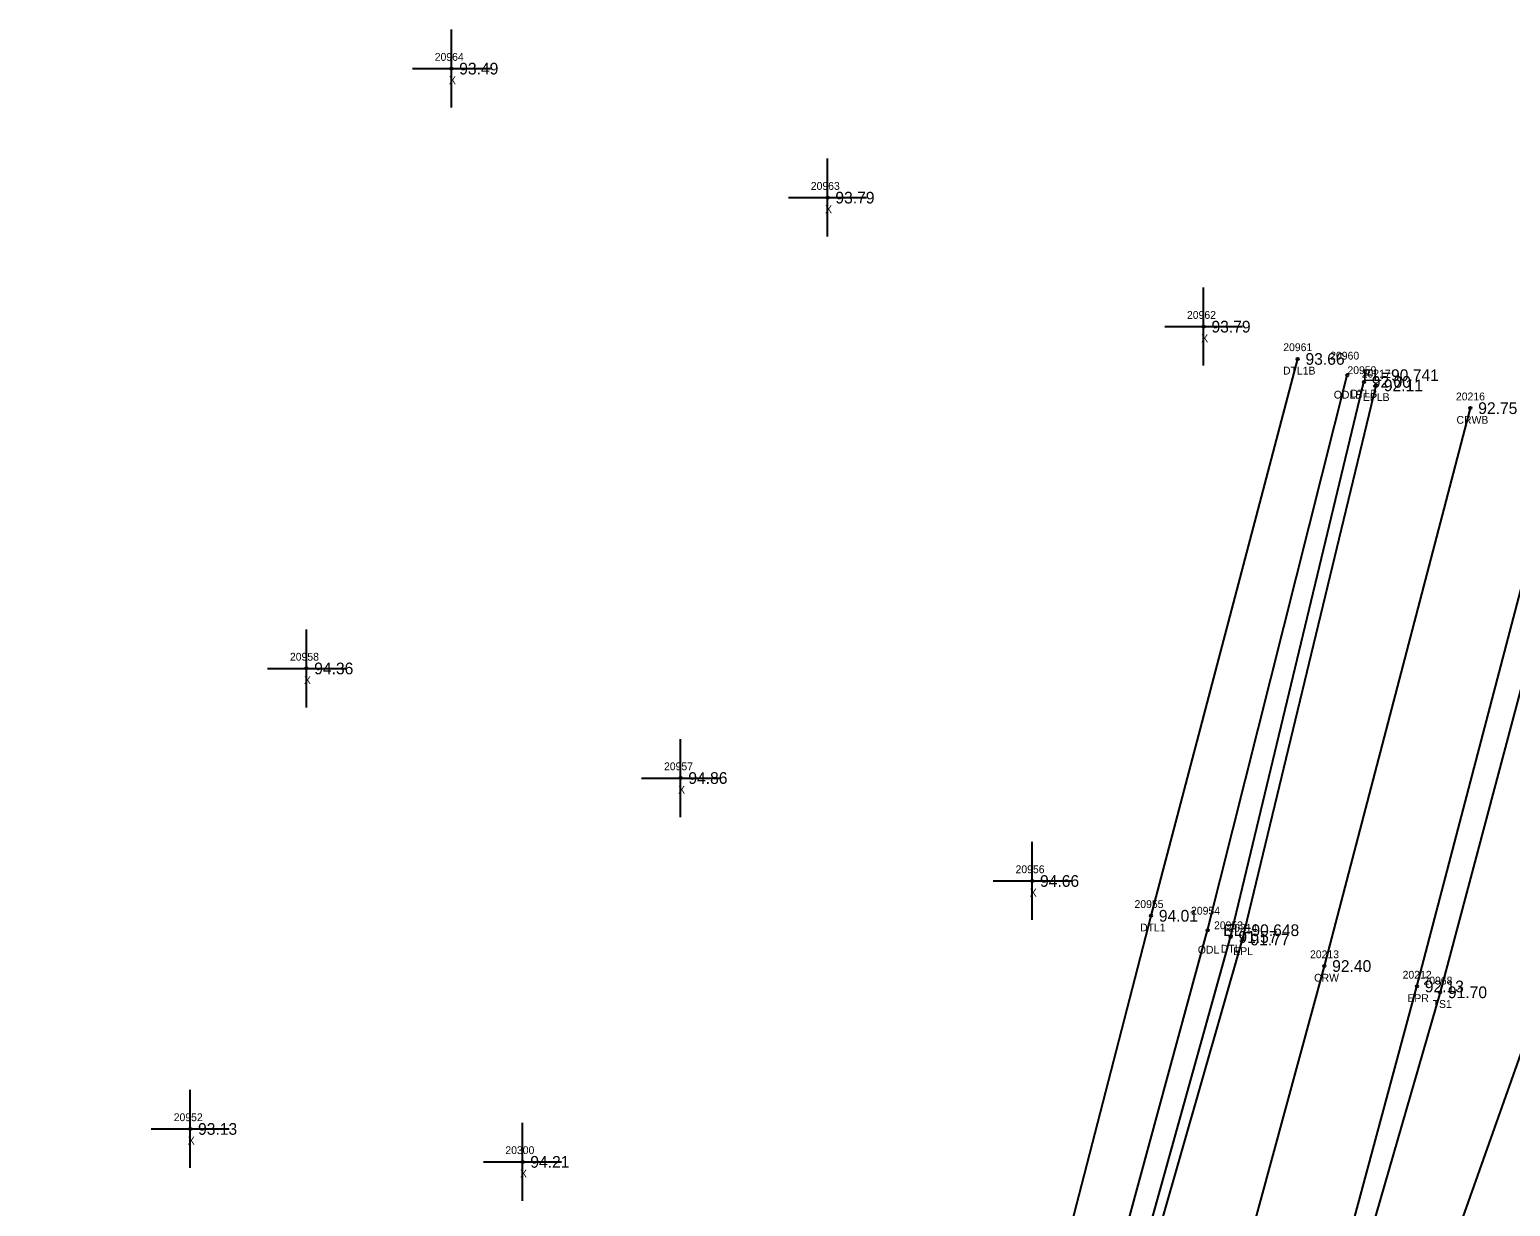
# Model space of a CAD drawing. Extents: x 2530197 to 2532051, y 935230 to 936631.
# Drawn here: x 2531647.6 to 2531837.5, y 936480.5 to 936631.4 of the extents above; entities that cross this region are included whole.
import ezdxf

# ---------------------------------------------------------------- set-up
doc = ezdxf.new("R2010")
doc.units = 0
for name, color, linetype in [('RD_DTM_BkLn1', 7, 'Continuous'), ('RD_DTM_BkLn2', 7, 'Continuous'), ('RD_DTM_BkLn_txCode', 7, 'Continuous'), ('RD_EX_H2O', 7, 'Continuous'), ('RD_EX_H2O_txCode', 7, 'Continuous'), ('RD_EX_Misc', 7, 'Continuous'), ('RD_EX_Misc_txCode', 7, 'Continuous'), ('RD_EX_Road', 7, 'Continuous'), ('RD_EX_Road_txCode', 7, 'Continuous'), ('RD_EX_TX_H2O_ELEV', 7, 'Continuous'), ('RD_EX_TX_Misc_ELEV', 7, 'Continuous'), ('RD_EX_TX_Road_ELEV', 7, 'Continuous'), ('RD_HC_Survey_ELEV', 7, 'Continuous'), ('RD_HC_Survey_txCode', 7, 'Continuous'), ('RD_SMD_Locator', 7, 'Continuous')]:
    doc.layers.add(name, color=color, linetype=linetype)

msp = doc.modelspace()

# ---------------------------------------------------------------- linework, layer by layer
at = {"layer": 'RD_DTM_BkLn1'}
msp.add_lwpolyline([(2531175.16, 935992.09), (2531214.08, 936014.93), (2531297.2, 936064.16), (2531382.2, 936114.3), (2531466.12, 936163.77), (2531548.89, 936212.96), (2531632.55, 936261.89), (2531678, 936289.19), (2531722.34, 936315.93), (2531754.26, 936342.49), (2531759.78, 936349.83), (2531772.77, 936373.29), (2531778.96, 936389.71), (2531793.78, 936438.29), (2531813.65, 936511.36), (2531832.39, 936582.88)], dxfattribs=at)
at = {"layer": 'RD_DTM_BkLn2'}
for points in [[(2531847.31, 936578.71), (2531828.5, 936507.99), (2531807.07, 936433.9), (2531793.16, 936383.74), (2531787.14, 936359.39), (2531794.14, 936352.47)], [(2531858.76, 936574.82), (2531840.28, 936504.17), (2531814.37, 936431.07), (2531798.77, 936381.67), (2531794.1, 936358.42), (2531794.14, 936352.47)]]:
    msp.add_lwpolyline(points, dxfattribs=at)
at = {"layer": 'RD_EX_H2O'}
for points in [[(2531765.74, 936419.97), (2531768.07, 936430.45), (2531772.65, 936445.12), (2531791.42, 936517.8), (2531810.23, 936589.19)], [(2531765.74, 936419.97), (2531771.25, 936418.23), (2531776.62, 936427.07), (2531781.23, 936441.81), (2531801.62, 936515.08), (2531818.73, 936586.25)], [(2531770.23, 936422.22), (2531778.73, 936442.72), (2531798.67, 936515.95), (2531816.58, 936587.11)]]:
    msp.add_lwpolyline(points, dxfattribs=at)
at = {"layer": 'RD_EX_Misc'}
for p, q in [((2531701.68, 936621.41), (2531701.68, 936631.41)), ((2531696.68, 936626.41), (2531706.68, 936626.41)), ((2531749.93, 936604.87), (2531749.93, 936614.87)), ((2531744.93, 936609.87), (2531754.93, 936609.87)), ((2531798.17, 936588.33), (2531798.17, 936598.33)), ((2531793.17, 936593.33), (2531803.17, 936593.33)), ((2531683.08, 936544.51), (2531683.08, 936554.51)), ((2531678.08, 936549.51), (2531688.08, 936549.51)), ((2531731.07, 936530.46), (2531731.07, 936540.46)), ((2531726.07, 936535.46), (2531736.07, 936535.46)), ((2531776.18, 936517.26), (2531776.18, 936527.26)), ((2531771.18, 936522.26), (2531781.18, 936522.26)), ((2531668.18, 936485.47), (2531668.18, 936495.47)), ((2531710.8, 936481.25), (2531710.8, 936491.25)), ((2531663.18, 936490.47), (2531673.18, 936490.47)), ((2531705.8, 936486.25), (2531715.8, 936486.25))]:
    msp.add_line(p, q, dxfattribs=at)
at = {"layer": 'RD_EX_Road'}
for points in [[(2531169.65, 936000.77), (2531208.79, 936024.95), (2531292.04, 936074.02), (2531376.24, 936123.7), (2531460.37, 936174.49), (2531542.92, 936223.44), (2531626.67, 936270.85), (2531672.4, 936298.39), (2531714.28, 936327.21), (2531747.19, 936360.45), (2531761.42, 936377.32), (2531773.11, 936411.11), (2531782.2, 936441.65), (2531803.17, 936514.76), (2531820.28, 936585.8)], [(2531180.82, 935982), (2531220.82, 936004.21), (2531303.54, 936053.39), (2531388.75, 936103.71), (2531472.27, 936152.98), (2531554.79, 936201.9), (2531638.11, 936250.92), (2531683.19, 936278.28), (2531730.37, 936304.55), (2531771.5, 936341.26), (2531788.67, 936375.53), (2531805.57, 936434.84), (2531825.53, 936508.74), (2531844.13, 936579.65)]]:
    msp.add_lwpolyline(points, dxfattribs=at)
at = {"layer": 'RD_SMD_Locator'}
for centre in [(2531701.68, 936626.41), (2531749.93, 936609.87), (2531798.17, 936593.33), (2531810.23, 936589.19), (2531816.58, 936587.11), (2531818.73, 936586.25), (2531820.28, 936585.8), (2531832.39, 936582.88), (2531683.08, 936549.51), (2531731.07, 936535.46), (2531776.18, 936522.26), (2531791.42, 936517.8), (2531798.67, 936515.95), (2531801.62, 936515.08), (2531803.17, 936514.76), (2531813.65, 936511.36), (2531825.53, 936508.74), (2531828.5, 936507.99), (2531668.18, 936490.47), (2531710.8, 936486.25)]:
    msp.add_circle(centre, 0.15, dxfattribs=at)

# ---------------------------------------------------------------- texts
at = {"layer": 'RD_DTM_BkLn_txCode'}
for s, p in [('20968', (2531826.36, 936508.99)), ('TS1', (2531827.54, 936505.99))]:
    msp.add_text(s, height=1, dxfattribs=at).set_placement(p)
at = {"layer": 'RD_EX_H2O_txCode'}
for s, p in [('20961', (2531808.38, 936590.19)), ('20960', (2531814.4, 936589.11)), ('DTL1B', (2531808.35, 936587.19)), ('20959', (2531816.61, 936587.25)), ('ODLB', (2531814.86, 936584.11)), ('DTLB', (2531817.02, 936584.25)), ('20955', (2531789.3, 936518.8)), ('20954', (2531796.55, 936517.95)), ('DTL1', (2531790.01, 936515.8)), ('20953', (2531799.5, 936516.08)), ('ODL', (2531797.42, 936512.95)), ('DTL', (2531800.37, 936513.08))]:
    msp.add_text(s, height=1, dxfattribs=at).set_placement(p)
at = {"layer": 'RD_EX_Misc_txCode'}
for s, p in [('20964', (2531699.54, 936627.41)), ('X', (2531701.37, 936624.41)), ('20963', (2531747.78, 936610.87)), ('X', (2531749.61, 936607.87)), ('20962', (2531796.03, 936594.33)), ('X', (2531797.85, 936591.33)), ('20958', (2531680.97, 936550.51)), ('X', (2531682.77, 936547.51)), ('20957', (2531728.95, 936536.46)), ('X', (2531730.76, 936533.46)), ('20956', (2531774.04, 936523.26)), ('X', (2531775.86, 936520.26)), ('20952', (2531666.06, 936491.47)), ('X', (2531667.86, 936488.47)), ('20300', (2531708.6, 936487.25)), ('X', (2531710.48, 936484.25))]:
    msp.add_text(s, height=1, dxfattribs=at).set_placement(p)
at = {"layer": 'RD_EX_Road_txCode'}
for s, p in [('20217', (2531818.44, 936586.8)), ('EPLB', (2531818.6, 936583.8)), ('20214', (2531801.34, 936515.76)), ('EPL', (2531801.97, 936512.76)), ('20212', (2531823.69, 936509.74)), ('EPR', (2531824.3, 936506.74))]:
    msp.add_text(s, height=1, dxfattribs=at).set_placement(p)
at = {"layer": 'RD_EX_TX_H2O_ELEV'}
for s, p in [('93.66', (2531811.23, 936588.44)), ('EL=90.741', (2531818.58, 936586.36)), ('92.00', (2531819.73, 936585.5)), ('94.01', (2531792.42, 936517.05)), ('EL=90.648', (2531800.67, 936515.2)), ('91.57', (2531802.62, 936514.33))]:
    msp.add_text(s, height=1.5, dxfattribs=at).set_placement(p)
at = {"layer": 'RD_EX_TX_Misc_ELEV'}
for s, p in [('93.49', (2531702.68, 936625.66)), ('93.79', (2531750.93, 936609.12)), ('93.79', (2531799.17, 936592.58)), ('94.36', (2531684.08, 936548.76)), ('94.86', (2531732.07, 936534.71)), ('94.66', (2531777.18, 936521.51)), ('91.70', (2531829.5, 936507.24)), ('93.13', (2531669.18, 936489.72)), ('94.21', (2531711.8, 936485.5))]:
    msp.add_text(s, height=1.5, dxfattribs=at).set_placement(p)
at = {"layer": 'RD_EX_TX_Road_ELEV'}
for s, p in [('92.11', (2531821.28, 936585.05)), ('91.77', (2531804.17, 936514.01)), ('92.13', (2531826.53, 936507.99))]:
    msp.add_text(s, height=1.5, dxfattribs=at).set_placement(p)
at = {"layer": 'RD_HC_Survey_ELEV'}
for s, p in [('92.75', (2531833.39, 936582.13)), ('92.40', (2531814.65, 936510.61))]:
    msp.add_text(s, height=1.5, dxfattribs=at).set_placement(p)
at = {"layer": 'RD_HC_Survey_txCode'}
for s, p in [('20216', (2531830.53, 936583.88)), ('CRWB', (2531830.6, 936580.88)), ('20213', (2531811.81, 936512.36)), ('CRW', (2531812.33, 936509.36))]:
    msp.add_text(s, height=1, dxfattribs=at).set_placement(p)

doc.saveas('drawing.dxf')
